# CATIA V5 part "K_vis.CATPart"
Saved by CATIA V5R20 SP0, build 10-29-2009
Part number: vis
Publications: "Plan.1", "Point.1"
Bounding box of the stored display mesh (mm): x -12.5 to 12.5, y 87.5 to 112.5, z -30.5 to 38.1
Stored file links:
  G:\Khaled_CFAO_2011\SIL\SIL_GR2\mdupuis\Khaled\CAD_ThinkMOTION\K_vis.CATPart
  G:\Dupuis_Maxime_Thinkmotion_CFAO\assemblage.CATProduct
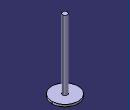
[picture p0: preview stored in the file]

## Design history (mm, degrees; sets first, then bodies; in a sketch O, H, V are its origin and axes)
Set1
  Plane1: linked copy from another document
  Point1: linked copy from another document
Body1 (main body)
  Sketch1 on Plane1, origin (0, 0, -30), H (1, 0, 0), V (0, 1, 0)
    circle A1 centre (0, 100) radius 12.5
    radius A1 = 12.5
  Pad1: profile Sketch1, direction (0, 0, 1), length 2
  Sketch2 on end face of Pad1, origin (0, 0, -28), H (1, 0, 0), V (0, 1, 0)
    circle A1 centre (0, 100) radius 2.25
    point P1 (0, 100)
    radius A1 = 2.25
    coincidence: P1 V
  Pad2: profile Sketch2, direction (0, 0, 1), length 66.1
  Sketch3 on start face of Pad1, origin (0, 0, -30), H (1, 0, 0), V (0, -1, 0)
    circle A1 centre (0, -100) radius 2.5
    point P1 (0, -100)
    radius A1 = 2.5
    coincidence: P1 V
  Pad3: profile Sketch3, direction (0, 0, -1), length 0.5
